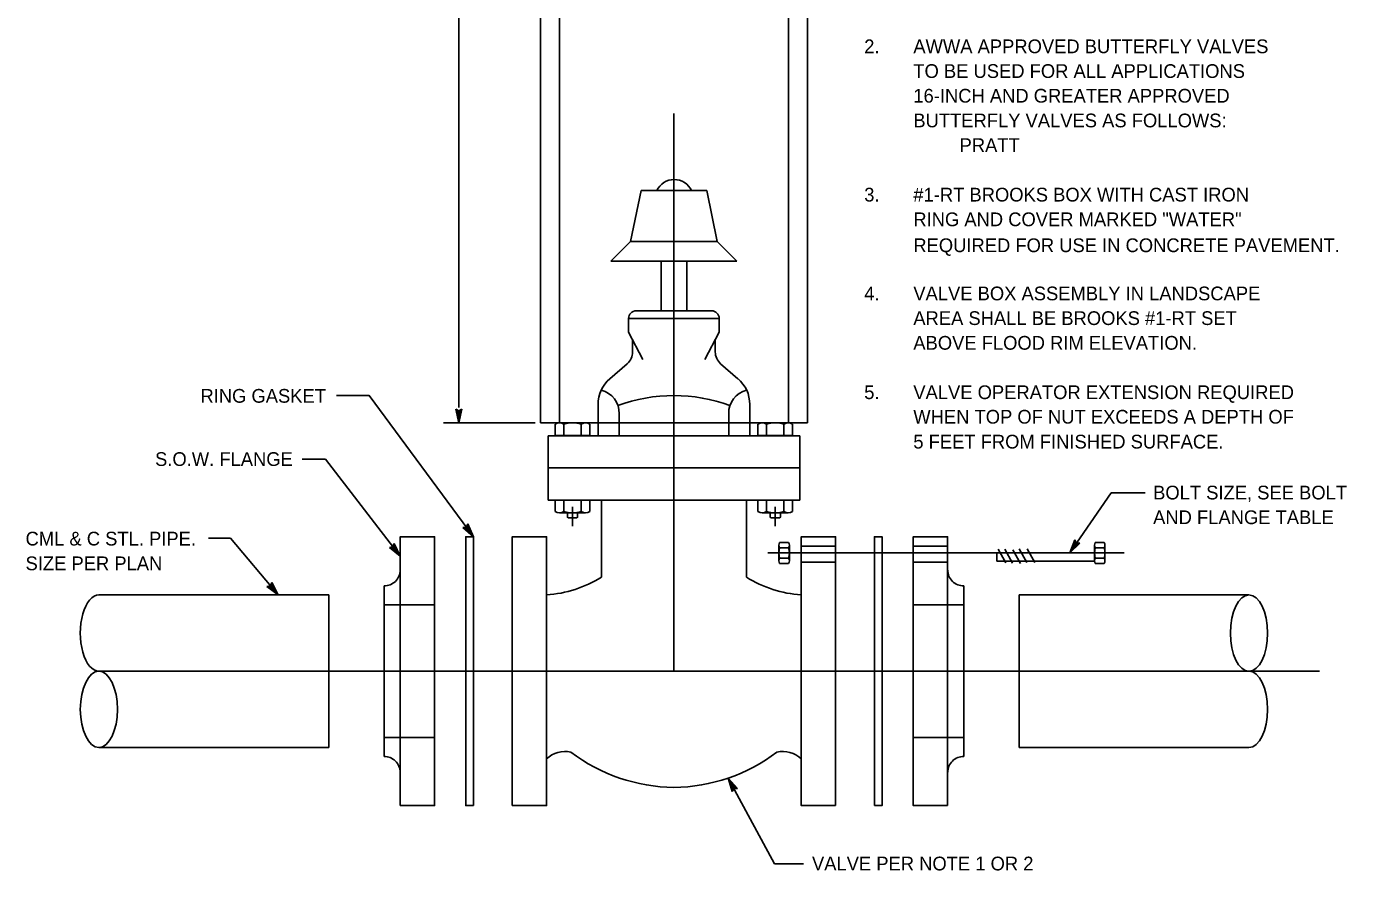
# Model space of a CAD drawing. Extents: x -121933 to -117742, y -103160 to -100084.
# Drawn here: x -121881 to -121304, y -101913 to -101544 of the extents above; entities that cross this region are included whole.
import ezdxf

# ---------------------------------------------------------------- set-up
doc = ezdxf.new("R2010")
doc.units = 0
for name, color, linetype in [('G-MARK', 7, 'Continuous'), ('G-TEXT', 7, 'Continuous'), ('Misc CnstDet(22)', 7, 'Continuous')]:
    doc.layers.add(name, color=color, linetype=linetype)

msp = doc.modelspace()

# ---------------------------------------------------------------- linework, layer by layer
at = {"layer": 'G-MARK'}
for p, q in [((-121692.28, -101349.26), (-121692.28, -101710.92)), ((-121658.98, -101717.59), (-121698.94, -101717.59))]:
    msp.add_line(p, q, dxfattribs=at)
for points in [[(-121685.92, -101767.38), (-121731.44, -101705.72), (-121745.82, -101705.72)], [(-121717.9, -101775.92), (-121750.61, -101733.42), (-121760.82, -101733.42)], [(-121425.4, -101774.47), (-121407.28, -101748.22), (-121392.48, -101748.22)], [(-121771.23, -101792.8), (-121792.07, -101768.01), (-121801.65, -101768.01)], [(-121574.6, -101872.82), (-121554.36, -101910.3), (-121541.65, -101910.3)]]:
    msp.add_lwpolyline(points, dxfattribs=at)
at = {"layer": 'G-TEXT'}
for p, q in [((-121692.28, -101717.59), (-121693.61, -101711.59)), ((-121693.61, -101711.59), (-121692.28, -101712.39)), ((-121693.6, -101711.59), (-121693.6, -101711.59)), ((-121692.28, -101716.2), (-121693.25, -101711.83)), ((-121692.27, -101714.83), (-121692.9, -101712)), ((-121692.28, -101712.39), (-121690.94, -101711.59)), ((-121690.94, -101711.59), (-121692.28, -101717.59)), ((-121691.29, -101711.81), (-121692.27, -101716.21)), ((-121690.94, -101711.59), (-121690.94, -101711.59)), ((-121692.27, -101713.45), (-121692.54, -101712.24)), ((-121691.65, -101712.04), (-121692.27, -101714.83)), ((-121692, -101712.22), (-121692.27, -101713.45)), ((-121692.28, -101717.59), (-121692.28, -101717.59)), ((-121690.53, -101763.32), (-121688.98, -101763.18)), ((-121685.92, -101767.38), (-121690.53, -101763.32)), ((-121690.53, -101763.32), (-121690.53, -101763.32)), ((-121686.74, -101766.26), (-121690.1, -101763.3)), ((-121687.55, -101765.15), (-121689.72, -101763.24)), ((-121688.36, -101764.03), (-121689.29, -101763.21)), ((-121688.98, -101763.18), (-121688.37, -101761.75)), ((-121688.86, -101762.88), (-121688.36, -101764.03)), ((-121688.69, -101762.53), (-121687.55, -101765.15)), ((-121688.53, -101762.13), (-121686.73, -101766.27)), ((-121688.37, -101761.75), (-121688.37, -101761.75)), ((-121688.37, -101761.75), (-121685.92, -101767.38)), ((-121685.92, -101767.38), (-121685.92, -101767.38)), ((-121425.4, -101774.47), (-121423.18, -101768.73)), ((-121424.63, -101773.31), (-121423.01, -101769.13)), ((-121423.87, -101772.17), (-121422.82, -101769.47)), ((-121423.18, -101768.74), (-121423.18, -101768.74)), ((-121423.18, -101768.74), (-121422.52, -101770.14)), ((-121722.64, -101772.01), (-121721.09, -101771.82)), ((-121717.9, -101775.92), (-121722.64, -101772.01)), ((-121722.64, -101772.01), (-121722.64, -101772.01)), ((-121718.76, -101774.83), (-121722.21, -101771.97)), ((-121719.6, -101773.74), (-121721.82, -101771.9)), ((-121720.44, -101772.65), (-121721.4, -101771.86)), ((-121721.09, -101771.82), (-121720.53, -101770.37)), ((-121720.98, -101771.51), (-121720.44, -101772.65)), ((-121720.82, -101771.16), (-121719.6, -101773.74)), ((-121720.68, -101770.76), (-121718.75, -101774.84)), ((-121720.53, -101770.37), (-121720.53, -101770.37)), ((-121720.53, -101770.37), (-121717.9, -101775.92)), ((-121420.96, -101770.21), (-121425.4, -101774.47)), ((-121425.4, -101774.47), (-121425.4, -101774.47)), ((-121421.38, -101770.2), (-121424.63, -101773.32)), ((-121421.8, -101770.19), (-121423.87, -101772.17)), ((-121423.1, -101771.02), (-121422.65, -101769.86)), ((-121422.19, -101770.15), (-121423.1, -101771.02)), ((-121422.52, -101770.14), (-121420.96, -101770.21)), ((-121420.96, -101770.21), (-121420.96, -101770.21)), ((-121717.9, -101775.92), (-121717.9, -101775.92)), ((-121776.12, -101789.07), (-121774.59, -101788.83)), ((-121771.23, -101792.8), (-121776.12, -101789.07)), ((-121776.12, -101789.07), (-121776.12, -101789.07)), ((-121772.13, -101791.74), (-121775.69, -101789.02)), ((-121773.01, -101790.69), (-121775.32, -101788.93)), ((-121773.9, -101789.63), (-121774.89, -101788.88)), ((-121774.59, -101788.83), (-121774.08, -101787.35)), ((-121774.49, -101788.51), (-121773.9, -101789.63)), ((-121774.34, -101788.16), (-121773.01, -101790.69)), ((-121774.21, -101787.75), (-121772.12, -101791.75)), ((-121774.08, -101787.35), (-121774.08, -101787.35)), ((-121774.08, -101787.35), (-121771.23, -101792.8)), ((-121771.23, -101792.8), (-121771.23, -101792.8)), ((-121572.83, -101878.7), (-121574.6, -101872.82)), ((-121574.6, -101872.82), (-121574.6, -101872.82)), ((-121574.6, -101872.82), (-121570.5, -101877.4)), ((-121572.62, -101878.34), (-121573.92, -101874.02)), ((-121573.91, -101874.03), (-121570.93, -101877.37)), ((-121572.42, -101877.96), (-121573.25, -101875.23)), ((-121573.25, -101875.23), (-121571.32, -101877.38)), ((-121572.05, -101877.35), (-121572.83, -101878.7)), ((-121572.83, -101878.7), (-121572.83, -101878.7)), ((-121572.21, -101877.64), (-121572.57, -101876.43)), ((-121572.57, -101876.43), (-121571.74, -101877.35)), ((-121570.5, -101877.4), (-121572.05, -101877.35)), ((-121570.5, -101877.4), (-121570.5, -101877.4))]:
    msp.add_line(p, q, dxfattribs=at)
at = {"layer": 'Misc CnstDet(22)'}
for p, q in [((-121656.65, -101342.59), (-121656.65, -101717.59)), ((-121539.98, -101342.59), (-121539.98, -101717.59)), ((-121648.32, -101380.3), (-121648.32, -101717.59)), ((-121548.32, -101380.3), (-121548.32, -101717.59)), ((-121598.32, -101826.13), (-121598.32, -101582.38)), ((-121617.28, -101638.42), (-121612.69, -101616.13)), ((-121583.94, -101616.13), (-121612.69, -101616.13)), ((-121579.36, -101638.42), (-121583.94, -101616.13)), ((-121617.28, -101638.42), (-121625.82, -101646.97)), ((-121579.36, -101638.42), (-121617.28, -101638.42)), ((-121579.36, -101638.42), (-121570.82, -101646.97)), ((-121570.82, -101646.97), (-121625.82, -101646.97)), ((-121603.94, -101646.97), (-121603.94, -101668.63)), ((-121592.69, -101646.97), (-121592.69, -101668.63)), ((-121581.86, -101668.63), (-121614.78, -101668.63)), ((-121578.53, -101671.97), (-121618.11, -101671.97)), ((-121618.11, -101671.97), (-121618.11, -101678.01)), ((-121578.53, -101671.97), (-121578.53, -101678.01)), ((-121618.11, -101678.01), (-121611.86, -101689.88)), ((-121616.37, -101681.31), (-121616.37, -101686.65)), ((-121578.53, -101678.01), (-121584.78, -101689.88)), ((-121580.26, -101681.31), (-121580.26, -101686.65)), ((-121626.31, -101698.34), (-121618.73, -101691.79)), ((-121570.33, -101698.34), (-121577.91, -101691.79)), ((-121631.44, -101723.22), (-121631.44, -101709.55)), ((-121565.19, -101723.22), (-121565.19, -101709.55)), ((-121656.65, -101717.59), (-121539.98, -101717.59)), ((-121636.92, -101717.58), (-121648.29, -101717.58)), ((-121559.71, -101717.58), (-121548.34, -101717.58)), ((-121653.32, -101723.22), (-121543.32, -101723.22)), ((-121653.32, -101723.22), (-121653.32, -101751.34)), ((-121650.18, -101718.14), (-121650.18, -101723.21)), ((-121635.03, -101723.21), (-121650.18, -101723.21)), ((-121646.39, -101718.14), (-121646.39, -101723.21)), ((-121638.82, -101718.14), (-121638.82, -101723.21)), ((-121635.03, -101718.14), (-121635.03, -101723.21)), ((-121561.6, -101718.14), (-121561.6, -101723.21)), ((-121561.6, -101723.21), (-121546.45, -101723.21)), ((-121557.81, -101718.14), (-121557.81, -101723.21)), ((-121550.24, -101718.14), (-121550.24, -101723.21)), ((-121546.45, -101718.14), (-121546.45, -101723.21)), ((-121543.32, -101723.22), (-121543.32, -101751.34)), ((-121653.32, -101737.28), (-121543.32, -101737.28)), ((-121653.32, -101751.34), (-121543.32, -101751.34)), ((-121635.03, -101751.33), (-121650.18, -101751.33)), ((-121650.18, -101756.39), (-121650.18, -101751.33)), ((-121646.39, -101756.39), (-121646.39, -101751.33)), ((-121638.82, -101756.39), (-121638.82, -101751.33)), ((-121635.03, -101756.39), (-121635.03, -101751.33)), ((-121629.98, -101751.34), (-121629.98, -101785.09)), ((-121566.65, -101751.34), (-121566.65, -101785.09)), ((-121561.6, -101751.33), (-121546.45, -101751.33)), ((-121561.6, -101756.39), (-121561.6, -101751.33)), ((-121557.81, -101756.39), (-121557.81, -101751.33)), ((-121550.24, -101756.39), (-121550.24, -101751.33)), ((-121546.45, -101756.39), (-121546.45, -101751.33)), ((-121636.92, -101756.95), (-121648.29, -101756.95)), ((-121642.61, -101754.26), (-121642.61, -101762.8)), ((-121559.71, -101756.95), (-121548.34, -101756.95)), ((-121554.02, -101754.26), (-121554.02, -101762.8)), ((-121557.28, -101774.47), (-121401.65, -101774.47)), ((-121552.47, -101777.88), (-121552.47, -101771.06)), ((-121548.22, -101769.92), (-121552.13, -101769.92)), ((-121548.22, -101772.2), (-121552.13, -101772.2)), ((-121547.89, -101777.88), (-121547.89, -101771.06)), ((-121542.69, -101771.55), (-121527.69, -101771.55)), ((-121493.73, -101771.55), (-121478.73, -101771.55)), ((-121457.28, -101774.47), (-121457.28, -101778.01)), ((-121456.65, -101772.8), (-121453.32, -101778.84)), ((-121453.72, -101772.85), (-121450.39, -101778.89)), ((-121450.18, -101773.06), (-121446.84, -101779.1)), ((-121447.47, -101772.64), (-121444.14, -101778.68)), ((-121443.93, -101772.64), (-121440.59, -101778.68)), ((-121414.57, -101777.88), (-121414.57, -101771.06)), ((-121410.33, -101769.92), (-121414.24, -101769.92)), ((-121410.33, -101772.2), (-121414.24, -101772.2)), ((-121409.99, -101777.88), (-121409.99, -101771.06)), ((-121548.22, -101776.74), (-121552.13, -101776.74)), ((-121548.22, -101779.02), (-121552.13, -101779.02)), ((-121542.69, -101778.42), (-121527.69, -101778.42)), ((-121493.73, -101778.42), (-121478.73, -101778.42)), ((-121457.28, -101778.01), (-121414.56, -101778.01)), ((-121410.33, -101776.74), (-121414.24, -101776.74)), ((-121410.33, -101779.02), (-121414.24, -101779.02)), ((-121724.98, -101863.42), (-121724.98, -101788.85)), ((-121471.65, -101863.42), (-121471.65, -101788.85)), ((-121849.57, -101792.8), (-121749.15, -101792.8)), ((-121749.15, -101792.8), (-121749.15, -101859.47)), ((-121724.98, -101797.17), (-121702.9, -101797.17)), ((-121471.65, -101797.17), (-121493.73, -101797.17)), ((-121347.07, -101792.8), (-121447.48, -101792.8)), ((-121447.48, -101792.8), (-121447.48, -101859.47)), ((-121849.57, -101826.13), (-121316.23, -101826.13)), ((-121724.98, -101855.09), (-121702.9, -101855.09)), ((-121471.65, -101855.09), (-121493.73, -101855.09)), ((-121849.57, -101859.47), (-121749.15, -101859.47)), ((-121347.07, -101859.47), (-121447.48, -101859.47))]:
    msp.add_line(p, q, dxfattribs=at)
for points in [[(-121622.28, -101723.22), (-121622.28, -101713.63)], [(-121574.36, -101723.22), (-121574.36, -101713.63)], [(-121644.83, -101756.97), (-121644.83, -101758.84), (-121644.41, -101759.05), (-121642.61, -101759.05)], [(-121640.4, -101756.97), (-121640.4, -101758.84), (-121640.82, -101759.05), (-121642.61, -101759.05)], [(-121556.23, -101756.97), (-121556.23, -101758.84), (-121555.82, -101759.05), (-121554.02, -101759.05)], [(-121551.8, -101756.97), (-121551.8, -101758.84), (-121552.22, -101759.05), (-121554.02, -101759.05)], [(-121689.25, -101767.38), (-121689.25, -101826.13), (-121685.92, -101826.13), (-121685.92, -101767.38), (-121689.25, -101767.38)], [(-121507.38, -101767.38), (-121507.38, -101826.13), (-121510.71, -101826.13), (-121510.71, -101767.38), (-121507.38, -101767.38)], [(-121685.92, -101884.88), (-121685.92, -101826.13), (-121689.25, -101826.13), (-121689.25, -101884.88), (-121685.92, -101884.88)], [(-121510.71, -101884.88), (-121510.71, -101826.13), (-121507.38, -101826.13), (-121507.38, -101884.88), (-121510.71, -101884.88)]]:
    msp.add_lwpolyline(points, dxfattribs=at)
for points in [[(-121717.9, -101884.88), (-121702.9, -101884.88), (-121702.9, -101767.38), (-121717.9, -101767.38)], [(-121685.92, -101884.88), (-121685.92, -101767.38), (-121689.25, -101767.38), (-121689.25, -101884.88)], [(-121668.94, -101884.88), (-121653.94, -101884.88), (-121653.94, -101767.38), (-121668.94, -101767.38)], [(-121527.69, -101884.88), (-121542.69, -101884.88), (-121542.69, -101767.38), (-121527.69, -101767.38)], [(-121510.71, -101884.88), (-121510.71, -101767.38), (-121507.38, -101767.38), (-121507.38, -101884.88)], [(-121478.73, -101884.88), (-121493.73, -101884.88), (-121493.73, -101767.38), (-121478.73, -101767.38)]]:
    msp.add_lwpolyline(points, close=True, dxfattribs=at)
for centre, radius, start, end in [((-121598.21, -101619.65), 8.38, 24.82016, 155.17984), ((-121614.78, -101671.97), 3.33, 90, 180), ((-121581.86, -101671.97), 3.33, 0, 90), ((-121623.17, -101686.65), 6.79, 310.81508, 0), ((-121573.47, -101686.65), 6.79, 180, 229.18492), ((-121616.62, -101709.55), 14.82, 130.81508, 180), ((-121580.01, -101709.55), 14.82, 0, 49.18492), ((-121632.38, -101713.24), 10.11, 357.75398, 76.96357), ((-121598.32, -101776.37), 70.69, 69.75171, 110.24829), ((-121564.26, -101713.24), 10.11, 103.03643, 182.24602), ((-121648.29, -101721.07), 3.49, 57.13278, 122.86722), ((-121642.61, -101730.7), 13.12, 73.22135, 106.77865), ((-121636.92, -101721.07), 3.49, 57.13278, 122.86722), ((-121559.71, -101721.07), 3.49, 57.13278, 122.86722), ((-121554.02, -101730.7), 13.12, 73.22135, 106.77865), ((-121548.34, -101721.07), 3.49, 57.13278, 122.86722), ((-121648.29, -101753.46), 3.49, 237.13278, 302.86722), ((-121642.61, -101743.83), 13.12, 253.22135, 286.77865), ((-121636.92, -101753.46), 3.49, 237.13278, 302.86722), ((-121559.71, -101753.46), 3.49, 237.13278, 302.86722), ((-121554.02, -101743.83), 13.12, 253.22135, 286.77865), ((-121548.34, -101753.46), 3.49, 237.13278, 302.86722), ((-121550.37, -101771.06), 2.09, 147.13278, 212.86722), ((-121544.59, -101774.47), 7.87, 163.22135, 196.77865), ((-121549.98, -101771.06), 2.09, 327.13278, 32.86722), ((-121555.76, -101774.47), 7.87, 343.22135, 16.77865), ((-121412.48, -101771.06), 2.09, 147.13278, 212.86722), ((-121406.7, -101774.47), 7.87, 163.22135, 196.77865), ((-121412.09, -101771.06), 2.09, 327.13278, 32.86722), ((-121417.87, -101774.47), 7.87, 343.22135, 16.77865), ((-121550.37, -101777.88), 2.09, 147.13278, 212.86722), ((-121549.98, -101777.88), 2.09, 327.13278, 32.86722), ((-121412.48, -101777.88), 2.09, 147.13278, 212.86722), ((-121412.09, -101777.88), 2.09, 327.13278, 32.86722), ((-121724.86, -101781.95), 6.9, 268.95807, 0), ((-121657.66, -101740.15), 52.78, 274.04121, 301.62882), ((-121538.97, -101740.15), 52.78, 238.37118, 265.95879), ((-121471.78, -101781.95), 6.9, 180, 271.04193), ((-121646.03, -101872.49), 11.28, 76.10131, 134.59896), ((-121596.96, -101799.73), 77.27, 233.13541, 268.99579), ((-121599.67, -101799.73), 77.27, 271.00421, 306.86459), ((-121550.61, -101872.49), 11.28, 45.40104, 103.89869), ((-121724.86, -101870.32), 6.9, 0, 91.04193), ((-121471.78, -101870.32), 6.9, 88.95807, 180)]:
    msp.add_arc(centre, radius, start, end, dxfattribs=at)
for centre, start_param, end_param in [((-121849.57, -101809.47), 0, 3.141593), ((-121347.07, -101842.8), 3.141593, 6.283185)]:
    msp.add_ellipse(centre, major_axis=(0, 16.67), ratio=0.4875, start_param=start_param, end_param=end_param, dxfattribs=at)
for centre in [(-121347.07, -101809.47), (-121849.57, -101842.8)]:
    msp.add_ellipse(centre, major_axis=(0, 16.67), ratio=0.4875, dxfattribs=at)

# ---------------------------------------------------------------- texts
for s, p in [('2.', (-121515.18, -101556.09)), ('AWWA APPROVED BUTTERFLY VALVES', (-121493.72, -101556.09)), ('TO BE USED FOR ALL APPLICATIONS', (-121493.72, -101566.89)), ('16-INCH AND GREATER APPROVED', (-121493.72, -101577.68)), ('BUTTERFLY VALVES AS FOLLOWS:', (-121493.72, -101588.48)), ('PRATT', (-121473.51, -101599.27)), ('3.', (-121515.18, -101620.89)), ('#1-RT BROOKS BOX WITH CAST IRON', (-121493.72, -101620.89)), ('RING AND COVER MARKED "WATER"', (-121493.72, -101631.68)), ('REQUIRED FOR USE IN CONCRETE PAVEMENT.', (-121493.72, -101643.02)), ('4.', (-121515.18, -101664.07)), ('VALVE BOX ASSEMBLY IN LANDSCAPE', (-121493.72, -101664.07)), ('AREA SHALL BE BROOKS #1-RT SET', (-121493.72, -101674.86)), ('ABOVE FLOOD RIM ELEVATION.', (-121493.72, -101685.65)), ('RING GASKET', (-121805.19, -101708.82)), ('5.', (-121515.18, -101707.24)), ('VALVE OPERATOR EXTENSION REQUIRED', (-121493.72, -101707.24)), ('WHEN TOP OF NUT EXCEEDS A DEPTH OF', (-121493.72, -101717.95)), ('5 FEET FROM FINISHED SURFACE.', (-121493.72, -101728.83)), ('S.O.W. FLANGE', (-121825.02, -101736.44)), ('BOLT SIZE, SEE BOLT', (-121388.95, -101751.08)), ('AND FLANGE TABLE', (-121388.95, -101761.87)), ('CML & C STL. PIPE.', (-121881.61, -101771.21)), ('SIZE PER PLAN', (-121881.61, -101782.01)), ('VALVE PER NOTE 1 OR 2', (-121538, -101913.18))]:
    msp.add_text(s, height=6, dxfattribs=at).set_placement(p)

doc.saveas('drawing.dxf')
